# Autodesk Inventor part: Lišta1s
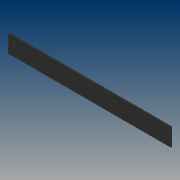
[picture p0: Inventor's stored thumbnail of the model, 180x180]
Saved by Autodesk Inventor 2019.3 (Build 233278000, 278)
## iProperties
Created: 2019-02
Part Number: Lišta1s
Material: PVC, nepoplastované
Document SubType Name: Modeling
Designer: B-hon
Density: 1.29 g/cm^3
Appearance: Guma – černá
Author: B-hon
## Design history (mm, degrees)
sketch "Náčrt1"
  geometry: L1 (352, -38)-(-352, -38); L2 (-352, -38)-(-352, 38); L3 (-352, 38)-(352, 38); L4 (352, 38)-(352, -38); L5 (352, -38)-(-352, 38); L6 (-352, -38)-(352, 38); 1 further point
  constraints: 12 end point, 2 midpoint, 2 parallel, 1 horizontal, 1 perpendicular
  dimensions: "d0" = 704 distance of L2.end L3.end; "d1" = 76 distance of L1.end L2.end
extrude "Vysunutí1" new body sketch "Náčrt1" distance "d2" = 5; taper "d3" = 0 deg
sketch "Náčrt2"
  geometry: L1 (-352, 38)-(-352, -38) reference; L2 (352, 38)-(-352, 38) reference; 2 further points
  dimensions: "d4" = 22 distance from line of L1 point (-330, 13); "d5" = 25 distance from line of point (-330, 13) L2
hole "Díra1" sketch "Náčrt2" at (-330, 13) diameter "d6" = 5.5; stored, may be unused: countersink angle "d10" = 90 deg, drill point angle "d12" = 0 deg; dims "d7" = 6, "d8" = 9.5, "d9" = 2, "d11" = 8
pattern_linear "Obdélníkové pole1" dims "d15" = 220
sketch "Náčrt3"
  geometry: L1 (-352, -38)-(352, -38) reference; L2 (-352, 38)-(-352, -38) reference; L3 (352, -38)-(352, 38) reference; 5 further points
  constraints: 2 horizontal alignment, 2 vertical alignment
  dimensions: "d16" = 7 distance from line of L1 point (-316, -31); "d17" = 36 distance from line of L2 point (-316, -13); "d18" = 36 distance from line of L3 point (316, -31); "d19" = 18 distance of point (-316, -13) point (-316, -31)
hole "Díra2" sketch "Náčrt3" at (-316, -31), (-316, -13), (316, -31), (316, -13) diameter "d20" = 5.5; stored, may be unused: countersink angle "d24" = 90 deg, drill point angle "d26" = 0 deg; dims "d21" = 6, "d22" = 9.5, "d23" = 2, "d25" = 8
node "Těleso1"
